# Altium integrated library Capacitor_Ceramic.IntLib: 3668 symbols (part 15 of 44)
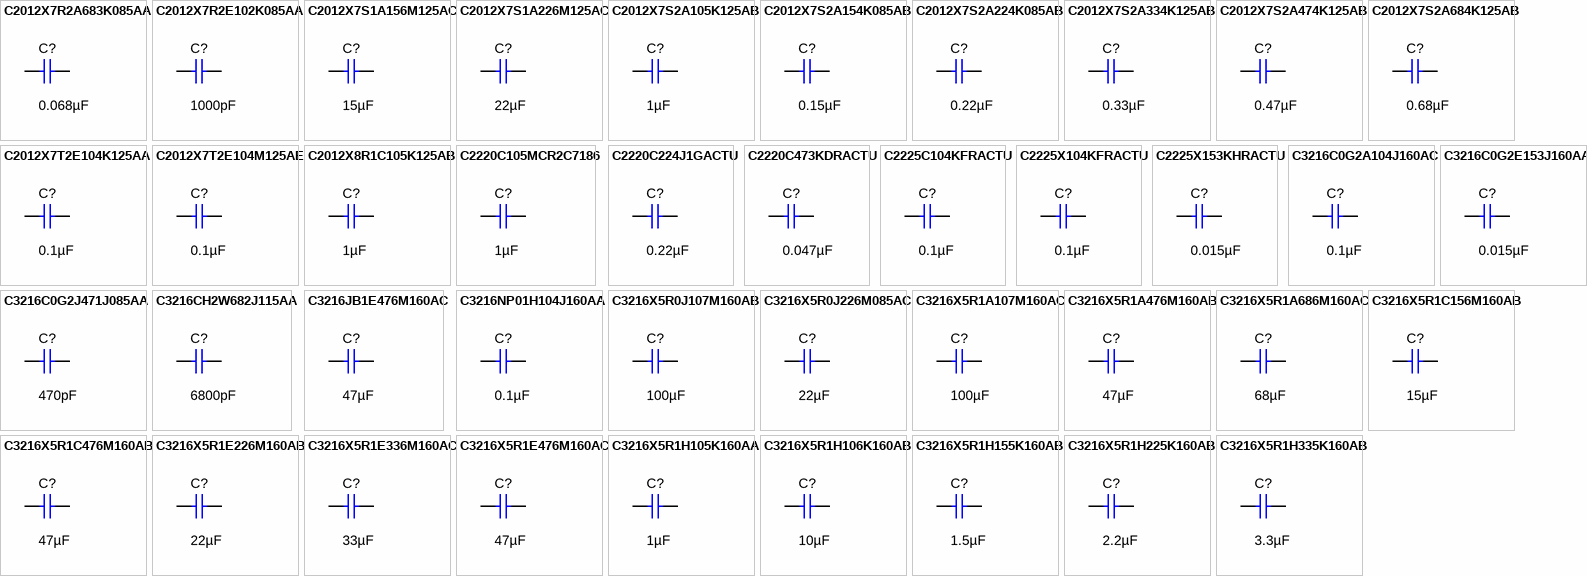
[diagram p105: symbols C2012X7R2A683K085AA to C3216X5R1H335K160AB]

## C2012X7R2A683K085AA
designator C?  ValueDisplayed: 0.068µF  (hidden comment: C2012X7R2A683K085AA)
CAP, CERM, 0.068 µF, 100 V,+/- 10%, X7R, 0805; Manufacturer: TDK; Polarized: N; CompType: Capacitor; Value: 0.068uF; U/M: EA; Cap_F: 0.000000068; Tolerance_%: 10; ESR_ohm: 0.027836; Value1: 0.027836 ohm; VDC_V: 100; Value2: 100V; IRMS_A: 1.26527; TaMin_C: -55; TaMax_C: 125; Cap_Case: 0805; SizeArea_mm2: 2.5; SizeAreaWB_mm2: 6.75; SizeX_mm: 2; SizeY_mm: 1.25; SizeZ_mm: 1.45; AEC Category: Q200
signal-integrity model Cap
simulation model Cap
footprint 0805_HV
footprint 0805_HV1
footprint 0805
footprint 0805M
footprint 0805L
pins: 1, 2

## C2012X7R2E102K085AA
designator C?  ValueDisplayed: 1000pF  (hidden comment: C2012X7R2E102K085AA)
CAP, CERM, 1000 pF, 250 V,+/- 10%, X7R, 0805; Manufacturer: TDK; Polarized: N; CompType: Capacitor; Value: 1000pF; U/M: EA; Cap_F: 0.000000001; Tolerance_%: 10; VDC_V: 250; Value2: 250V; TaMin_C: -55; TaMax_C: 125; Cap_Case: 0805; SizeArea_mm2: 2.5; SizeAreaWB_mm2: 6.75; SizeX_mm: 2; SizeY_mm: 1.25; SizeZ_mm: 1.45; AEC Category: Q200
signal-integrity model Cap
simulation model Cap
footprint 0805_HV
footprint 0805_HV1
footprint 0805
footprint 0805M
footprint 0805L
pins: 1, 2

## C2012X7S1A156M125AC
designator C?  ValueDisplayed: 15µF  (hidden comment: C2012X7S1A156M125AC)
CAP, CERM, 15 µF, 10 V,+/- 20%, X7S, 0805; Manufacturer: TDK; Polarized: N; CompType: Capacitor; Value: 15uF; U/M: EA; Cap_F: 0.000015; Tolerance_%: 20; ESR_ohm: 0.001669; Value1: 0.001669 ohm; VDC_V: 10; Value2: 10V; IRMS_A: 5.04984; TaMin_C: -55; TaMax_C: 125; Cap_Case: 0805; SizeArea_mm2: 2.5; SizeAreaWB_mm2: 6.75; SizeX_mm: 2; SizeY_mm: 1.25; SizeZ_mm: 1.45; AEC Category: Q200
signal-integrity model Cap
simulation model Cap
footprint 0805_HV
footprint 0805_HV1
footprint 0805
footprint 0805M
footprint 0805L
pins: 1, 2

## C2012X7S1A226M125AC
designator C?  ValueDisplayed: 22µF  (hidden comment: C2012X7S1A226M125AC)
CAP, CERM, 22 µF, 10 V,+/- 20%, X7S, 0805; Manufacturer: TDK; Polarized: N; CompType: Capacitor; Value: 22uF; U/M: EA; Cap_F: 0.000022; Tolerance_%: 20; ESR_ohm: 0.00205; Value1: 0.00205 ohm; VDC_V: 10; Value2: 10V; IRMS_A: 4.55587; TaMin_C: -55; TaMax_C: 125; Cap_Case: 0805; SizeArea_mm2: 2.5; SizeAreaWB_mm2: 6.75; SizeX_mm: 2; SizeY_mm: 1.25; SizeZ_mm: 1.45; AEC Category: Q200; Green_Lifecycle: Active; Green_REACh: Passed
signal-integrity model Cap
simulation model Cap
footprint 0805_HV
footprint 0805_HV1
footprint 0805
footprint 0805M
footprint 0805L
pins: 1, 2

## C2012X7S2A105K125AB
designator C?  ValueDisplayed: 1µF  (hidden comment: C2012X7S2A105K125AB)
CAP, CERM, 1 µF, 100 V,+/- 10%, X7S, 0805; Manufacturer: TDK; Polarized: N; CompType: Capacitor; Value: 1uF; U/M: EA; Cap_F: 0.000001; Tolerance_%: 10; ESR_ohm: 0.008255; Value1: 0.008255 ohm; VDC_V: 100; Value2: 100V; IRMS_A: 2.27442; TaMin_C: -55; TaMax_C: 125; Cap_Case: 0805; SizeArea_mm2: 2.5; SizeAreaWB_mm2: 6.75; SizeX_mm: 2; SizeY_mm: 1.25; SizeZ_mm: 1.45; AEC Category: Q200; Green_Lifecycle: Active; Green_REACh: Passed
signal-integrity model Cap
simulation model Cap
footprint 0805_HV
footprint 0805_HV1
footprint 0805
footprint 0805M
footprint 0805L
pins: 1, 2

## C2012X7S2A154K085AB
designator C?  ValueDisplayed: 0.15µF  (hidden comment: C2012X7S2A154K085AB)
CAP, CERM, 0.15 µF, 100 V,+/- 10%, X7S, 0805; Manufacturer: TDK; Polarized: N; CompType: Capacitor; Value: 0.15uF; U/M: EA; Cap_F: 0.00000015; Tolerance_%: 10; ESR_ohm: 0.043574; Value1: 0.043574 ohm; VDC_V: 100; Value2: 100V; IRMS_A: 0.999812; TaMin_C: -55; TaMax_C: 125; Cap_Case: 0805; SizeArea_mm2: 2.5; SizeAreaWB_mm2: 6.75; SizeX_mm: 2; SizeY_mm: 1.25; SizeZ_mm: 1.45; AEC Category: Q200
signal-integrity model Cap
simulation model Cap
footprint 0805_HV
footprint 0805_HV1
footprint 0805
footprint 0805M
footprint 0805L
pins: 1, 2

## C2012X7S2A224K085AB
designator C?  ValueDisplayed: 0.22µF  (hidden comment: C2012X7S2A224K085AB)
CAP, CERM, 0.22 µF, 100 V,+/- 10%, X7S, 0805; Manufacturer: TDK; Polarized: N; CompType: Capacitor; Value: 0.22uF; U/M: EA; Cap_F: 0.00000022; Tolerance_%: 10; ESR_ohm: 0.027015; Value1: 0.027015 ohm; VDC_V: 100; Value2: 100V; IRMS_A: 1.26497; TaMin_C: -55; TaMax_C: 125; Cap_Case: 0805; SizeArea_mm2: 2.5; SizeAreaWB_mm2: 6.75; SizeX_mm: 2; SizeY_mm: 1.25; SizeZ_mm: 1.45; AEC Category: Q200
signal-integrity model Cap
simulation model Cap
footprint 0805_HV
footprint 0805_HV1
footprint 0805
footprint 0805M
footprint 0805L
pins: 1, 2

## C2012X7S2A334K125AB
designator C?  ValueDisplayed: 0.33µF  (hidden comment: C2012X7S2A334K125AB)
CAP, CERM, 0.33 µF, 100 V,+/- 10%, X7S, 0805; Manufacturer: TDK; Polarized: N; CompType: Capacitor; Value: 0.33uF; U/M: EA; Cap_F: 0.00000033; Tolerance_%: 10; ESR_ohm: 0.019477; Value1: 0.019477 ohm; VDC_V: 100; Value2: 100V; IRMS_A: 1.48561; TaMin_C: -55; TaMax_C: 125; Cap_Case: 0805; SizeArea_mm2: 2.5; SizeAreaWB_mm2: 6.75; SizeX_mm: 2; SizeY_mm: 1.25; SizeZ_mm: 1.45; AEC Category: Q200
signal-integrity model Cap
simulation model Cap
footprint 0805_HV
footprint 0805_HV1
footprint 0805
footprint 0805M
footprint 0805L
pins: 1, 2

## C2012X7S2A474K125AB
designator C?  ValueDisplayed: 0.47µF  (hidden comment: C2012X7S2A474K125AB)
CAP, CERM, 0.47 µF, 100 V,+/- 10%, X7S, 0805; Manufacturer: TDK; Polarized: N; CompType: Capacitor; Value: 0.47uF; U/M: EA; Cap_F: 0.00000047; Tolerance_%: 10; ESR_ohm: 0.017152; Value1: 0.017152 ohm; VDC_V: 100; Value2: 100V; IRMS_A: 1.58068; TaMin_C: -55; TaMax_C: 125; Cap_Case: 0805; SizeArea_mm2: 2.5; SizeAreaWB_mm2: 6.75; SizeX_mm: 2; SizeY_mm: 1.25; SizeZ_mm: 1.45; AEC Category: Q200
signal-integrity model Cap
simulation model Cap
footprint 0805_HV
footprint 0805_HV1
footprint 0805
footprint 0805M
footprint 0805L
pins: 1, 2

## C2012X7S2A684K125AB
designator C?  ValueDisplayed: 0.68µF  (hidden comment: C2012X7S2A684K125AB)
CAP, CERM, 0.68 µF, 100 V,+/- 10%, X7S, 0805; Manufacturer: TDK; Polarized: N; CompType: Capacitor; Value: 0.68uF; U/M: EA; Cap_F: 0.00000068; Tolerance_%: 10; ESR_ohm: 0.009732; Value1: 0.009732 ohm; VDC_V: 100; Value2: 100V; IRMS_A: 2.09614; TaMin_C: -55; TaMax_C: 125; Cap_Case: 0805; SizeArea_mm2: 2.5; SizeAreaWB_mm2: 6.75; SizeX_mm: 2; SizeY_mm: 1.25; SizeZ_mm: 1.45; AEC Category: Q200
signal-integrity model Cap
simulation model Cap
footprint 0805_HV
footprint 0805_HV1
footprint 0805
footprint 0805M
footprint 0805L
pins: 1, 2

## C2012X7T2E104K125AA
designator C?  ValueDisplayed: 0.1µF  (hidden comment: C2012X7T2E104K125AA)
CAP, CERM, 0.1 µF, 250 V,+/- 10%, X7T, 0805; Manufacturer: TDK; Polarized: N; CompType: Capacitor; Value: 0.1uF; U/M: EA; Cap_F: 0.0000001; Tolerance_%: 10; VDC_V: 250; Value2: 250V; TaMin_C: -55; TaMax_C: 125; Cap_Case: 0805; SizeArea_mm2: 2.5; SizeAreaWB_mm2: 6.75; SizeX_mm: 2; SizeY_mm: 1.25; SizeZ_mm: 1.45; AEC Category: Q200
signal-integrity model Cap
simulation model Cap
footprint 0805_HV
footprint 0805_HV1
footprint 0805
footprint 0805M
footprint 0805L
pins: 1, 2

## C2012X7T2E104M125AE
designator C?  ValueDisplayed: 0.1µF  (hidden comment: C2012X7T2E104M125AE)
CAP, CERM, 0.1 µF, 250 V,+/- 20%, X7T, 0805; Manufacturer: TDK; Polarized: N; CompType: Capacitor; Value: 0.1uF; U/M: EA; Cap_F: 0.0000001; Tolerance_%: 20; VDC_V: 250; Value2: 250V; TaMin_C: -55; TaMax_C: 125; Cap_Case: 0805; SizeArea_mm2: 2.5; SizeAreaWB_mm2: 6.75; SizeX_mm: 2; SizeY_mm: 1.25; SizeZ_mm: 1.45; AEC Category: Q200
signal-integrity model Cap
simulation model Cap
footprint 0805_HV
footprint 0805_HV1
footprint 0805
footprint 0805M
footprint 0805L
pins: 1, 2

## C2012X8R1C105K125AB
designator C?  ValueDisplayed: 1µF  (hidden comment: C2012X8R1C105K125AB)
CAP, CERM, 1 µF, 16 V,+/- 10%, X8R, 0805; Manufacturer: TDK; Polarized: N; CompType: Capacitor; Value: 1uF; U/M: EA; Cap_F: 0.000001; Tolerance_%: 10; VDC_V: 16; Value2: 16V; TaMin_C: -55; TaMax_C: 150; Cap_Case: 0805; SizeArea_mm2: 2.5; SizeAreaWB_mm2: 6.75; SizeX_mm: 2; SizeY_mm: 1.25; SizeZ_mm: 1.45; AEC Category: Q200
signal-integrity model Cap
simulation model Cap
footprint 0805_HV
footprint 0805_HV1
footprint 0805
footprint 0805M
footprint 0805L
pins: 1, 2

## C2220C105MCR2C7186
designator C?  ValueDisplayed: 1µF  (hidden comment: C2220C105MCR2C7186)
CAP, CERM, 1 µF, 500 V,+/- 20%, X7R, AEC-Q200 Grade 1, 6x5mm; Manufacturer: Kemet; Polarized: N; CompType: Capacitor; Value: 1uF; U/M: EA; Cap_F: 0.000001; Tolerance_%: 20; VDC_V: 500; Value2: 500V; TaMin_C: -55; TaMax_C: 125; Cap_Case: 2220; SizeArea_mm2: 30; SizeAreaWB_mm2: 56; SizeX_mm: 6; SizeY_mm: 5; AEC Category: Q200; AEC Qualified: Y; AEC Grade: 1; Green_Lifecycle: Not Set; Green_REACh: Incomplete
signal-integrity model Cap
simulation model Cap
footprint KPS_600x500x500
pins: 1, 2

## C2220C224J1GACTU
designator C?  ValueDisplayed: 0.22µF  (hidden comment: C2220C224J1GACTU)
CAP, CERM, 0.22 µF, 100 V,+/- 5%, C0G/NP0, 2220; Manufacturer: Kemet; Polarized: N; CompType: Capacitor; Value: 0.22uF; U/M: EA; Cap_F: 0.00000022; Tolerance_%: 5; VDC_V: 100; Value2: 100V; TaMin_C: -55; TaMax_C: 125; Cap_Case: 2220; SizeArea_mm2: 28.5; SizeAreaWB_mm2: 53.9; SizeX_mm: 5.7; SizeZ_mm: 1.5; AEC Category: Q200; Green_Lifecycle: Active; Green_REACh: Passed
signal-integrity model Cap
simulation model Cap
footprint 2220_150
footprint 2220_150M
footprint 2220_150L
pins: 1, 2

## C2220C473KDRACTU
designator C?  ValueDisplayed: 0.047µF  (hidden comment: C2220C473KDRACTU)
CAP, CERM, 0.047 µF, 1000 V,+/- 10%, X7R, 2220; Manufacturer: Kemet; Polarized: N; CompType: Capacitor; Value: 0.047uF; U/M: EA; Cap_F: 0.000000047; Tolerance_%: 10; VDC_V: 1000; Value2: 1000V; TaMin_C: -55; TaMax_C: 125; Cap_Case: 2220; SizeArea_mm2: 28.5; SizeAreaWB_mm2: 53.9; SizeX_mm: 5.7; SizeY_mm: 5; SizeZ_mm: 1.8; AEC Category: Q200; Green_Lifecycle: Not Set; Green_REACh: Incomplete
signal-integrity model Cap
simulation model Cap
footprint 2220_180
footprint 2220_180M
footprint 2220_180L
pins: 1, 2

## C2225C104KFRACTU
designator C?  ValueDisplayed: 0.1µF  (hidden comment: C2225C104KFRACTU)
CAP, CERM, 0.1 µF, 1500 V,+/- 10%, X7R, 2225; Manufacturer: Kemet; Polarized: N; CompType: Capacitor; Value: 0.1uF; U/M: EA; Cap_F: 0.0000001; Tolerance_%: 10; VDC_V: 1500; Value2: 1500V; TaMin_C: -55; TaMax_C: 125; Cap_Case: 2225; SizeArea_mm2: 35.91; SizeAreaWB_mm2: 63.91; SizeX_mm: 5.7; SizeY_mm: 6.3; SizeZ_mm: 2; AEC Category: Q200; Green_Lifecycle: Not Set; Green_REACh: Incomplete
signal-integrity model Cap
simulation model Cap
footprint 2225
footprint 2225_M
footprint 2225_L
pins: 1, 2

## C2225X104KFRACTU
designator C?  ValueDisplayed: 0.1µF  (hidden comment: C2225X104KFRACTU)
CAP, CERM, 0.1 µF, 1500 V,+/- 10%, X7R, 2225; Manufacturer: Kemet; Polarized: N; CompType: Capacitor; Value: 0.1uF; U/M: EA; Cap_F: 0.0000001; Tolerance_%: 10; VDC_V: 1500; Value2: 1500V; TaMin_C: -55; TaMax_C: 125; Cap_Case: 2225; SizeArea_mm2: 35.91; SizeAreaWB_mm2: 63.91; SizeX_mm: 5.7; SizeY_mm: 6.3; SizeZ_mm: 2.7; AEC Category: Q200; Green_Lifecycle: Not Set; Green_REACh: Incomplete
signal-integrity model Cap
simulation model Cap
footprint 2225_270
footprint 2225_270_M
footprint 2225_270_L
pins: 1, 2

## C2225X153KHRACTU
designator C?  ValueDisplayed: 0.015µF  (hidden comment: C2225X153KHRACTU)
CAP, CERM, 0.015 µF, 3000 V,+/- 10%, X7R, 2225; Manufacturer: Kemet; Polarized: N; CompType: Capacitor; Value: 0.015uF; U/M: EA; Cap_F: 0.000000015; Tolerance_%: 10; VDC_V: 3000; Value2: 3000V; TaMin_C: -55; TaMax_C: 125; Cap_Case: 2225; SizeArea_mm2: 35.91; SizeAreaWB_mm2: 63.91; SizeX_mm: 5.7; SizeY_mm: 6.3; SizeZ_mm: 2.7; AEC Category: Q200; Green_Lifecycle: Not Set; Green_REACh: Incomplete
signal-integrity model Cap
simulation model Cap
footprint 2225_270
footprint 2225_270_M
footprint 2225_270_L
pins: 1, 2

## C3216C0G2A104J160AC
designator C?  ValueDisplayed: 0.1µF  (hidden comment: C3216C0G2A104J160AC)
CAP, CERM, 0.1 µF, 100 V,+/- 5%, C0G/NP0, 1206; Manufacturer: TDK; Polarized: N; CompType: Capacitor; Value: 0.1uF; U/M: EA; Cap_F: 0.0000001; Tolerance_%: 5; VDC_V: 100; Value2: 100V; TaMin_C: -55; TaMax_C: 125; Cap_Case: 1206; SizeArea_mm2: 5.12; SizeAreaWB_mm2: 10.92; SizeX_mm: 3.2; SizeY_mm: 1.6; SizeZ_mm: 1.9; AEC Category: Q200
signal-integrity model Cap
simulation model Cap
footprint 1206_190
footprint 1206_190M
footprint 1206_190L
pins: 1, 2

## C3216C0G2E153J160AA
designator C?  ValueDisplayed: 0.015µF  (hidden comment: C3216C0G2E153J160AA)
CAP, CERM, 0.015 µF, 250 V,+/- 5%, C0G/NP0, 1206; Manufacturer: TDK; Polarized: N; CompType: Capacitor; Value: 0.015uF; U/M: EA; Cap_F: 0.000000015; Tolerance_%: 5; VDC_V: 250; Value2: 250V; TaMin_C: -55; TaMax_C: 125; Cap_Case: 1206; SizeArea_mm2: 5.12; SizeAreaWB_mm2: 10.92; SizeX_mm: 3.2; SizeY_mm: 1.6; SizeZ_mm: 1.9; AEC Category: Q200
signal-integrity model Cap
simulation model Cap
footprint 1206_190
footprint 1206_190M
footprint 1206_190L
pins: 1, 2

## C3216C0G2J471J085AA
designator C?  ValueDisplayed: 470pF  (hidden comment: C3216C0G2J471J085AA)
CAP, CERM, 470 pF, 630 V,+/- 5%, C0G/NP0, 1206; Manufacturer: TDK; Polarized: N; CompType: Capacitor; Value: 470pF; U/M: EA; Cap_F: 0.00000000047; Tolerance_%: 5; VDC_V: 630; Value2: 630V; TaMin_C: -55; TaMax_C: 125; Cap_Case: 1206; SizeArea_mm2: 5.12; SizeAreaWB_mm2: 10.92; SizeX_mm: 3.2; SizeY_mm: 1.6; SizeZ_mm: 1.35; AEC Category: Q200; Green_Lifecycle: Active; Green_REACh: Passed
signal-integrity model Cap
simulation model Cap
footprint 1206
footprint 1206M
footprint 1206L
pins: 1, 2

## C3216CH2W682J115AA
designator C?  ValueDisplayed: 6800pF  (hidden comment: C3216CH2W682J115AA)
CAP, CERM, 6800 pF, 450 V,+/- 5%, CH, 1206; Manufacturer: TDK; Polarized: N; CompType: Capacitor; Value: 6800pF; U/M: EA; Cap_F: 0.0000000068; Tolerance_%: 5; VDC_V: 450; Value2: 450V; TaMin_C: -25; TaMax_C: 85; Cap_Case: 1206; SizeArea_mm2: 5.12; SizeAreaWB_mm2: 10.92; SizeX_mm: 3.2; SizeY_mm: 1.6; SizeZ_mm: 1.4; AEC Category: Q200
signal-integrity model Cap
simulation model Cap
footprint 1206_140
footprint 1206_140M
footprint 1206_140L
pins: 1, 2

## C3216JB1E476M160AC
designator C?  ValueDisplayed: 47µF  (hidden comment: C3216JB1E476M160AC)
CAP, CERM, 47 µF, 25 V,+/- 20%, JB, 1206; Manufacturer: TDK; Polarized: N; CompType: Capacitor; Value: 47uF; U/M: EA; Cap_F: 0.000047; Tolerance_%: 20; VDC_V: 25; Value2: 25V; TaMin_C: -55; TaMax_C: 85; Cap_Case: 1206; SizeArea_mm2: 5.12; SizeAreaWB_mm2: 10.92; SizeX_mm: 3.2; SizeY_mm: 1.6; SizeZ_mm: 1.35; AEC Category: Q200
signal-integrity model Cap
simulation model Cap
footprint 1206
footprint 1206M
footprint 1206L
pins: 1, 2

## C3216NP01H104J160AA
designator C?  ValueDisplayed: 0.1µF  (hidden comment: C3216NP01H104J160AA)
CAP, CERM, 0.1 µF, 50 V,+/- 5%, C0G/NP0, 1206; Manufacturer: TDK; Polarized: N; CompType: Capacitor; Value: 0.1uF; U/M: EA; Cap_F: 0.0000001; Tolerance_%: 5; VDC_V: 50; Value2: 50V; TaMin_C: -55; TaMax_C: 150; Cap_Case: 1206; SizeArea_mm2: 5.12; SizeAreaWB_mm2: 10.92; SizeX_mm: 3.2; SizeY_mm: 1.6; SizeZ_mm: 1.9; AEC Category: Q200
signal-integrity model Cap
simulation model Cap
footprint 1206_190
footprint 1206_190M
footprint 1206_190L
pins: 1, 2

## C3216X5R0J107M160AB
designator C?  ValueDisplayed: 100µF  (hidden comment: C3216X5R0J107M160AB)
CAP, CERM, 100 µF, 6.3 V,+/- 20%, X5R, 1206; Manufacturer: TDK; Polarized: N; CompType: Capacitor; Value: 100uF; U/M: EA; Cap_F: 0.0001; Tolerance_%: 20; VDC_V: 6.3; Value2: 6.3V; TaMin_C: -55; TaMax_C: 85; Cap_Case: 1206; SizeArea_mm2: 5.12; SizeAreaWB_mm2: 10.92; SizeX_mm: 3.2; SizeY_mm: 1.6; SizeZ_mm: 1.9; AEC Category: Q200; Green_Lifecycle: Active; Green_REACh: Passed
signal-integrity model Cap
simulation model Cap
footprint 1206_190
footprint 1206_190M
footprint 1206_190L
pins: 1, 2

## C3216X5R0J226M085AC
designator C?  ValueDisplayed: 22µF  (hidden comment: C3216X5R0J226M085AC)
CAP, CERM, 22 µF, 6.3 V,+/- 20%, X5R, 1206; Manufacturer: TDK; Polarized: N; CompType: Capacitor; Value: 22uF; U/M: EA; Cap_F: 0.000022; Tolerance_%: 20; ESR_ohm: 0.002; Value1: 0.002 ohm; VDC_V: 6.3; Value2: 6.3V; IRMS_A: 3.62; TaMin_C: -55; TaMax_C: 85; Cap_Case: 1206; SizeArea_mm2: 5.12; SizeAreaWB_mm2: 10.92; SizeX_mm: 3.2; SizeY_mm: 1.6; SizeZ_mm: 1.35; AEC Category: Q200; Green_Lifecycle: NRND; Green_REACh: Passed
signal-integrity model Cap
simulation model Cap
footprint 1206
footprint 1206M
footprint 1206L
pins: 1, 2

## C3216X5R1A107M160AC
designator C?  ValueDisplayed: 100µF  (hidden comment: C3216X5R1A107M160AC)
CAP, CERM, 100 µF, 10 V,+/- 20%, X5R, 1206; Manufacturer: TDK; Polarized: N; CompType: Capacitor; Value: 100uF; U/M: EA; Cap_F: 0.0001; Tolerance_%: 20; ESR_ohm: 0.002838; Value1: 0.002838 ohm; VDC_V: 10; Value2: 10V; IRMS_A: 4.30694; TaMin_C: -55; TaMax_C: 85; Cap_Case: 1206; SizeArea_mm2: 5.12; SizeAreaWB_mm2: 10.92; SizeX_mm: 3.2; SizeY_mm: 1.6; SizeZ_mm: 1.9; AEC Category: Q200; Green_Lifecycle: Active; Green_REACh: Passed
signal-integrity model Cap
simulation model Cap
footprint 1206_190
footprint 1206_190M
footprint 1206_190L
pins: 1, 2

## C3216X5R1A476M160AB
designator C?  ValueDisplayed: 47µF  (hidden comment: C3216X5R1A476M160AB)
CAP, CERM, 47 µF, 10 V,+/- 20%, X5R, 1206; Manufacturer: TDK; Polarized: N; CompType: Capacitor; Value: 47uF; U/M: EA; Cap_F: 0.000047; Tolerance_%: 20; VDC_V: 10; Value2: 10V; TaMin_C: -55; TaMax_C: 85; Cap_Case: 1206; SizeArea_mm2: 5.12; SizeAreaWB_mm2: 10.92; SizeX_mm: 3.2; SizeY_mm: 1.6; SizeZ_mm: 1.8; AEC Category: Q200
signal-integrity model Cap
simulation model Cap
footprint 1206_180
footprint 1206_180M
footprint 1206_180L
pins: 1, 2

## C3216X5R1A686M160AC
designator C?  ValueDisplayed: 68µF  (hidden comment: C3216X5R1A686M160AC)
CAP, CERM, 68 µF, 10 V,+/- 20%, X5R, 1206; Manufacturer: TDK; Polarized: N; CompType: Capacitor; Value: 68uF; U/M: EA; Cap_F: 0.000068; Tolerance_%: 20; ESR_ohm: 0.003494; Value1: 0.003494 ohm; VDC_V: 10; Value2: 10V; IRMS_A: 3.8813; TaMin_C: -55; TaMax_C: 85; Cap_Case: 1206; SizeArea_mm2: 5.12; SizeAreaWB_mm2: 10.92; SizeX_mm: 3.2; SizeY_mm: 1.6; SizeZ_mm: 1.9; AEC Category: Q200
signal-integrity model Cap
simulation model Cap
footprint 1206_190
footprint 1206_190M
footprint 1206_190L
pins: 1, 2

## C3216X5R1C156M160AB
designator C?  ValueDisplayed: 15µF  (hidden comment: C3216X5R1C156M160AB)
CAP, CERM, 15 µF, 16 V,+/- 20%, X5R, 1206; Manufacturer: TDK; Polarized: N; CompType: Capacitor; Value: 15uF; U/M: EA; Cap_F: 0.000015; Tolerance_%: 20; VDC_V: 16; Value2: 16V; TaMin_C: -55; TaMax_C: 85; Cap_Case: 1206; SizeArea_mm2: 5.12; SizeAreaWB_mm2: 10.92; SizeX_mm: 3.2; SizeY_mm: 1.6; SizeZ_mm: 1.8; AEC Category: Q200; Green_Lifecycle: Not Set; Green_REACh: Incomplete
signal-integrity model Cap
simulation model Cap
footprint 1206_180
footprint 1206_180M
footprint 1206_180L
pins: 1, 2

## C3216X5R1C476M160AB
designator C?  ValueDisplayed: 47µF  (hidden comment: C3216X5R1C476M160AB)
CAP, CERM, 47 µF, 16 V,+/- 15%, X5R, 1206; Manufacturer: TDK; Polarized: N; CompType: Capacitor; Value: 47uF; U/M: EA; Cap_F: 0.000047; Tolerance_%: 15; VDC_V: 16; Value2: 16V; TaMin_C: -55; TaMax_C: 85; Cap_Case: 1206; SizeArea_mm2: 5.12; SizeAreaWB_mm2: 10.92; SizeX_mm: 3.2; SizeY_mm: 1.6; SizeZ_mm: 1.35; AEC Category: Q200; Green_Lifecycle: Active; Green_REACh: Passed
signal-integrity model Cap
simulation model Cap
footprint 1206
footprint 1206M
footprint 1206L
pins: 1, 2

## C3216X5R1E226M160AB
designator C?  ValueDisplayed: 22µF  (hidden comment: C3216X5R1E226M160AB)
CAP, CERM, 22 µF, 25 V,+/- 20%, X5R, 1206; Manufacturer: TDK; Polarized: N; CompType: Capacitor; Value: 22uF; U/M: EA; Cap_F: 0.000022; Tolerance_%: 20; VDC_V: 25; Value2: 25V; TaMin_C: -55; TaMax_C: 85; Cap_Case: 1206; SizeArea_mm2: 5.12; SizeAreaWB_mm2: 10.92; SizeX_mm: 3.2; SizeY_mm: 1.6; SizeZ_mm: 1.9; AEC Category: Q200; Green_Lifecycle: Active; Green_REACh: Passed
signal-integrity model Cap
simulation model Cap
footprint 1206_190
footprint 1206_190M
footprint 1206_190L
pins: 1, 2

## C3216X5R1E336M160AC
designator C?  ValueDisplayed: 33µF  (hidden comment: C3216X5R1E336M160AC)
CAP, CERM, 33 µF, 25 V,+/- 20%, X5R, 1206; Manufacturer: TDK; Polarized: N; CompType: Capacitor; Value: 33uF; U/M: EA; Cap_F: 0.000033; Tolerance_%: 20; ESR_ohm: 0.002648; Value1: 0.002648 ohm; VDC_V: 25; Value2: 25V; IRMS_A: 4.45864; TaMin_C: -55; TaMax_C: 85; Cap_Case: 1206; SizeArea_mm2: 5.12; SizeAreaWB_mm2: 10.92; SizeX_mm: 3.2; SizeY_mm: 1.6; SizeZ_mm: 1.8; AEC Category: Q200; Green_Lifecycle: Active; Green_REACh: Passed
signal-integrity model Cap
simulation model Cap
footprint 1206_180
footprint 1206_180M
footprint 1206_180L
pins: 1, 2

## C3216X5R1E476M160AC
designator C?  ValueDisplayed: 47µF  (hidden comment: C3216X5R1E476M160AC)
CAP, CERM, 47 µF, 25 V,+/- 20%, X5R, 1206; Manufacturer: TDK; Polarized: N; CompType: Capacitor; Value: 47uF; U/M: EA; Cap_F: 0.000047; Tolerance_%: 20; VDC_V: 25; Value2: 25V; TaMin_C: -55; TaMax_C: 85; Cap_Case: 1206; SizeArea_mm2: 5.12; SizeAreaWB_mm2: 10.92; SizeX_mm: 3.2; SizeY_mm: 1.6; SizeZ_mm: 1.9; AEC Category: Q200; Green_Lifecycle: Active; Green_REACh: Passed
signal-integrity model Cap
simulation model Cap
footprint 1206_190
footprint 1206_190M
footprint 1206_190L
pins: 1, 2

## C3216X5R1H105K160AA
designator C?  ValueDisplayed: 1µF  (hidden comment: C3216X5R1H105K160AA)
CAP, CERM, 1 µF, 50 V,+/- 10%, X5R, 1206; Manufacturer: TDK; Polarized: N; CompType: Capacitor; Value: 1uF; U/M: EA; Cap_F: 0.000001; Tolerance_%: 10; ESR_ohm: 0.009289; Value1: 0.009289 ohm; VDC_V: 50; Value2: 50V; IRMS_A: 2.38446; TaMin_C: -55; TaMax_C: 85; Cap_Case: 1206; SizeArea_mm2: 5.12; SizeAreaWB_mm2: 10.92; SizeX_mm: 3.2; SizeY_mm: 1.6; SizeZ_mm: 1.8; AEC Category: Q200
signal-integrity model Cap
simulation model Cap
footprint 1206_180
footprint 1206_180M
footprint 1206_180L
pins: 1, 2

## C3216X5R1H106K160AB
designator C?  ValueDisplayed: 10µF  (hidden comment: C3216X5R1H106K160AB)
CAP, CERM, 10 µF, 50 V,+/- 10%, X5R, 1206; Manufacturer: TDK; Polarized: N; CompType: Capacitor; Value: 10uF; U/M: EA; Cap_F: 0.00001; Tolerance_%: 10; ESR_ohm: 0.002229; Value1: 0.002229 ohm; VDC_V: 50; Value2: 50V; IRMS_A: 4.85932; TaMin_C: -55; TaMax_C: 85; Cap_Case: 1206; SizeArea_mm2: 5.12; SizeAreaWB_mm2: 10.92; SizeX_mm: 3.2; SizeY_mm: 1.6; SizeZ_mm: 1.8; AEC Category: Q200; Green_Lifecycle: Active; Green_REACh: Passed
signal-integrity model Cap
simulation model Cap
footprint 1206_180
footprint 1206_180M
footprint 1206_180L
pins: 1, 2

## C3216X5R1H155K160AB
designator C?  ValueDisplayed: 1.5µF  (hidden comment: C3216X5R1H155K160AB)
CAP, CERM, 1.5 µF, 50 V,+/- 10%, X5R, 1206; Manufacturer: TDK; Polarized: N; CompType: Capacitor; Value: 1.5uF; U/M: EA; Cap_F: 0.0000015; Tolerance_%: 10; ESR_ohm: 0.007741; Value1: 0.007741 ohm; VDC_V: 50; Value2: 50V; IRMS_A: 2.61033; TaMin_C: -55; TaMax_C: 85; Cap_Case: 1206; SizeArea_mm2: 5.12; SizeAreaWB_mm2: 10.92; SizeX_mm: 3.2; SizeY_mm: 1.6; SizeZ_mm: 1.8; AEC Category: Q200
signal-integrity model Cap
simulation model Cap
footprint 1206_180
footprint 1206_180M
footprint 1206_180L
pins: 1, 2

## C3216X5R1H225K160AB
designator C?  ValueDisplayed: 2.2µF  (hidden comment: C3216X5R1H225K160AB)
CAP, CERM, 2.2 µF, 50 V,+/- 10%, X5R, 1206; Manufacturer: TDK; Polarized: N; CompType: Capacitor; Value: 2.2uF; U/M: EA; Cap_F: 0.0000022; Tolerance_%: 10; ESR_ohm: 0.005887; Value1: 0.005887 ohm; VDC_V: 50; Value2: 50V; IRMS_A: 2.99226; TaMin_C: -55; TaMax_C: 85; Cap_Case: 1206; SizeArea_mm2: 5.12; SizeAreaWB_mm2: 10.92; SizeX_mm: 3.2; SizeY_mm: 1.6; SizeZ_mm: 1.8; AEC Category: Q200
signal-integrity model Cap
simulation model Cap
footprint 1206_180
footprint 1206_180M
footprint 1206_180L
pins: 1, 2

## C3216X5R1H335K160AB
designator C?  ValueDisplayed: 3.3µF  (hidden comment: C3216X5R1H335K160AB)
CAP, CERM, 3.3 µF, 50 V,+/- 10%, X5R, 1206; Manufacturer: TDK; Polarized: N; CompType: Capacitor; Value: 3.3uF; U/M: EA; Cap_F: 0.0000033; Tolerance_%: 10; ESR_ohm: 0.004773; Value1: 0.004773 ohm; VDC_V: 50; Value2: 50V; IRMS_A: 3.3221; TaMin_C: -55; TaMax_C: 85; Cap_Case: 1206; SizeArea_mm2: 5.12; SizeAreaWB_mm2: 10.92; SizeX_mm: 3.2; SizeY_mm: 1.6; SizeZ_mm: 1.8; AEC Category: Q200
signal-integrity model Cap
simulation model Cap
footprint 1206_180
footprint 1206_180M
footprint 1206_180L
pins: 1, 2

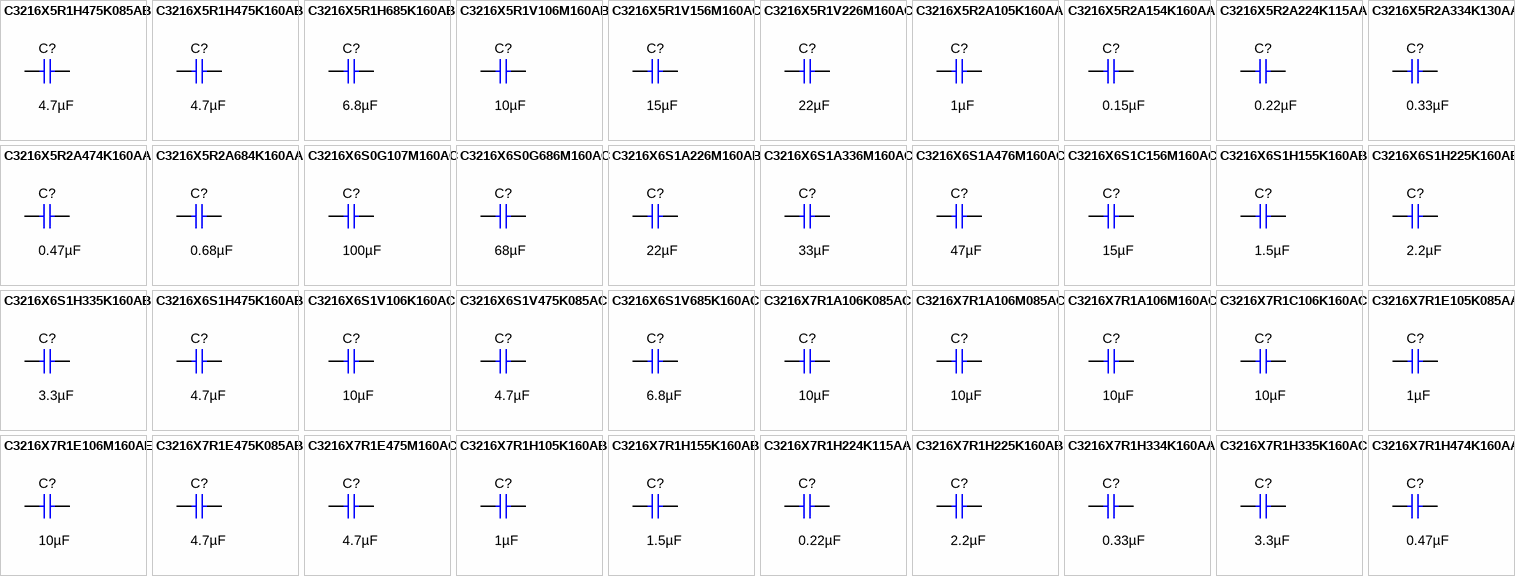
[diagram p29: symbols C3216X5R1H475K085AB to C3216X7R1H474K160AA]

## C3216X5R1H475K085AB
designator C?  ValueDisplayed: 4.7µF  (hidden comment: C3216X5R1H475K085AB)
CAP, CERM, 4.7 µF, 50 V,+/- 10%, X5R, 1206; Manufacturer: TDK; Polarized: N; CompType: Capacitor; Value: 4.7uF; U/M: EA; Cap_F: 0.0000047; Tolerance_%: 10; ESR_ohm: 0.003785; Value1: 0.003785 ohm; VDC_V: 50; Value2: 50V; IRMS_A: 3.73011; TaMin_C: -55; TaMax_C: 85; Cap_Case: 1206; SizeArea_mm2: 5.12; SizeAreaWB_mm2: 10.92; SizeX_mm: 3.2; SizeY_mm: 1.6; SizeZ_mm: 1.35; AEC Category: Q200
signal-integrity model Cap
simulation model Cap
footprint 1206
footprint 1206M
footprint 1206L
pins: 1, 2

## C3216X5R1H475K160AB
designator C?  ValueDisplayed: 4.7µF  (hidden comment: C3216X5R1H475K160AB)
CAP, CERM, 4.7 µF, 50 V,+/- 10%, X5R, 1206; Manufacturer: TDK; Polarized: N; CompType: Capacitor; Value: 4.7uF; U/M: EA; Cap_F: 0.0000047; Tolerance_%: 10; ESR_ohm: 0.003158; Value1: 0.003158 ohm; VDC_V: 50; Value2: 50V; IRMS_A: 4.08379; TaMin_C: -55; TaMax_C: 85; Cap_Case: 1206; SizeArea_mm2: 5.12; SizeAreaWB_mm2: 10.92; SizeX_mm: 3.2; SizeY_mm: 1.6; SizeZ_mm: 1.8; AEC Category: Q200
signal-integrity model Cap
simulation model Cap
footprint 1206_180
footprint 1206_180M
footprint 1206_180L
pins: 1, 2

## C3216X5R1H685K160AB
designator C?  ValueDisplayed: 6.8µF  (hidden comment: C3216X5R1H685K160AB)
CAP, CERM, 6.8 µF, 50 V,+/- 10%, X5R, 1206; Manufacturer: TDK; Polarized: N; CompType: Capacitor; Value: 6.8uF; U/M: EA; Cap_F: 0.0000068; Tolerance_%: 10; ESR_ohm: 0.003202; Value1: 0.003202 ohm; VDC_V: 50; Value2: 50V; IRMS_A: 4.05527; TaMin_C: -55; TaMax_C: 85; Cap_Case: 1206; SizeArea_mm2: 5.12; SizeAreaWB_mm2: 10.92; SizeX_mm: 3.2; SizeY_mm: 1.6; SizeZ_mm: 1.8; AEC Category: Q200
signal-integrity model Cap
simulation model Cap
footprint 1206_180
footprint 1206_180M
footprint 1206_180L
pins: 1, 2

## C3216X5R1V106M160AB
designator C?  ValueDisplayed: 10µF  (hidden comment: C3216X5R1V106M160AB)
CAP, CERM, 10 µF, 35 V,+/- 20%, X5R, 1206; Manufacturer: TDK; Polarized: N; CompType: Capacitor; Value: 10uF; U/M: EA; Cap_F: 0.00001; Tolerance_%: 20; VDC_V: 35; Value2: 35V; TaMin_C: -55; TaMax_C: 85; Cap_Case: 1206; SizeArea_mm2: 5.12; SizeAreaWB_mm2: 10.92; SizeX_mm: 3.2; SizeY_mm: 1.6; SizeZ_mm: 1.8; AEC Category: Q200; Green_Lifecycle: Not Set; Green_REACh: Incomplete
signal-integrity model Cap
simulation model Cap
footprint 1206_180
footprint 1206_180M
footprint 1206_180L
pins: 1, 2

## C3216X5R1V156M160AC
designator C?  ValueDisplayed: 15µF  (hidden comment: C3216X5R1V156M160AC)
CAP, CERM, 15 µF, 35 V,+/- 20%, X5R, 1206; Manufacturer: TDK; Polarized: N; CompType: Capacitor; Value: 15uF; U/M: EA; Cap_F: 0.000015; Tolerance_%: 20; ESR_ohm: 0.002667; Value1: 0.002667 ohm; VDC_V: 35; Value2: 35V; IRMS_A: 4.44289; TaMin_C: -55; TaMax_C: 85; Cap_Case: 1206; SizeArea_mm2: 5.12; SizeAreaWB_mm2: 10.92; SizeX_mm: 3.2; SizeY_mm: 1.6; SizeZ_mm: 1.8; AEC Category: Q200
signal-integrity model Cap
simulation model Cap
footprint 1206_180
footprint 1206_180M
footprint 1206_180L
pins: 1, 2

## C3216X5R1V226M160AC
designator C?  ValueDisplayed: 22µF  (hidden comment: C3216X5R1V226M160AC)
CAP, CERM, 22 µF, 35 V,+/- 20%, X5R, 1206; Manufacturer: TDK; Polarized: N; CompType: Capacitor; Value: 22uF; U/M: EA; Cap_F: 0.000022; Tolerance_%: 20; ESR_ohm: 0.002398; Value1: 0.002398 ohm; VDC_V: 35; Value2: 35V; IRMS_A: 4.68507; TaMin_C: -55; TaMax_C: 85; Cap_Case: 1206; SizeArea_mm2: 5.12; SizeAreaWB_mm2: 10.92; SizeX_mm: 3.2; SizeY_mm: 1.6; SizeZ_mm: 1.8; AEC Category: Q200; Green_Lifecycle: Active; Green_REACh: Passed
signal-integrity model Cap
simulation model Cap
footprint 1206_180
footprint 1206_180M
footprint 1206_180L
pins: 1, 2

## C3216X5R2A105K160AA
designator C?  ValueDisplayed: 1µF  (hidden comment: C3216X5R2A105K160AA)
CAP, CERM, 1 µF, 100 V,+/- 10%, X5R, 1206; Manufacturer: TDK; Polarized: N; CompType: Capacitor; Value: 1uF; U/M: EA; Cap_F: 0.000001; Tolerance_%: 10; ESR_ohm: 0.004575; Value1: 0.004575 ohm; VDC_V: 100; Value2: 100V; IRMS_A: 3.39639; TaMin_C: -55; TaMax_C: 85; Cap_Case: 1206; SizeArea_mm2: 5.12; SizeAreaWB_mm2: 10.92; SizeX_mm: 3.2; SizeY_mm: 1.6; SizeZ_mm: 1.8; AEC Category: Q200
signal-integrity model Cap
simulation model Cap
footprint 1206_180
footprint 1206_180M
footprint 1206_180L
pins: 1, 2

## C3216X5R2A154K160AA
designator C?  ValueDisplayed: 0.15µF  (hidden comment: C3216X5R2A154K160AA)
CAP, CERM, 0.15 µF, 100 V,+/- 10%, X5R, 1206; Manufacturer: TDK; Polarized: N; CompType: Capacitor; Value: 0.15uF; U/M: EA; Cap_F: 0.00000015; Tolerance_%: 10; ESR_ohm: 0.021684; Value1: 0.021684 ohm; VDC_V: 100; Value2: 100V; IRMS_A: 1.57495; TaMin_C: -55; TaMax_C: 85; Cap_Case: 1206; SizeArea_mm2: 5.12; SizeAreaWB_mm2: 10.92; SizeX_mm: 3.2; SizeY_mm: 1.6; SizeZ_mm: 1.8; AEC Category: Q200
signal-integrity model Cap
simulation model Cap
footprint 1206_180
footprint 1206_180M
footprint 1206_180L
pins: 1, 2

## C3216X5R2A224K115AA
designator C?  ValueDisplayed: 0.22µF  (hidden comment: C3216X5R2A224K115AA)
CAP, CERM, 0.22 µF, 100 V,+/- 10%, X5R, 1206; Manufacturer: TDK; Polarized: N; CompType: Capacitor; Value: 0.22uF; U/M: EA; Cap_F: 0.00000022; Tolerance_%: 10; ESR_ohm: 0.01493; Value1: 0.01493 ohm; VDC_V: 100; Value2: 100V; IRMS_A: 1.89056; TaMin_C: -55; TaMax_C: 85; Cap_Case: 1206; SizeArea_mm2: 5.12; SizeAreaWB_mm2: 10.92; SizeX_mm: 3.2; SizeY_mm: 1.6; SizeZ_mm: 1.35; AEC Category: Q200
signal-integrity model Cap
simulation model Cap
footprint 1206
footprint 1206M
footprint 1206L
pins: 1, 2

## C3216X5R2A334K130AA
designator C?  ValueDisplayed: 0.33µF  (hidden comment: C3216X5R2A334K130AA)
CAP, CERM, 0.33 µF, 100 V,+/- 10%, X5R, 1206; Manufacturer: TDK; Polarized: N; CompType: Capacitor; Value: 0.33uF; U/M: EA; Cap_F: 0.00000033; Tolerance_%: 10; ESR_ohm: 0.011504; Value1: 0.011504 ohm; VDC_V: 100; Value2: 100V; IRMS_A: 2.14919; TaMin_C: -55; TaMax_C: 85; Cap_Case: 1206; SizeArea_mm2: 5.12; SizeAreaWB_mm2: 10.92; SizeX_mm: 3.2; SizeY_mm: 1.6; SizeZ_mm: 1.5; AEC Category: Q200
signal-integrity model Cap
simulation model Cap
footprint 1206_150
footprint 1206_150M
footprint 1206_150L
pins: 1, 2

## C3216X5R2A474K160AA
designator C?  ValueDisplayed: 0.47µF  (hidden comment: C3216X5R2A474K160AA)
CAP, CERM, 0.47 µF, 100 V,+/- 10%, X5R, 1206; Manufacturer: TDK; Polarized: N; CompType: Capacitor; Value: 0.47uF; U/M: EA; Cap_F: 0.00000047; Tolerance_%: 10; ESR_ohm: 0.007558; Value1: 0.007558 ohm; VDC_V: 100; Value2: 100V; IRMS_A: 2.64716; TaMin_C: -55; TaMax_C: 85; Cap_Case: 1206; SizeArea_mm2: 5.12; SizeAreaWB_mm2: 10.92; SizeX_mm: 3.2; SizeY_mm: 1.6; SizeZ_mm: 1.8; AEC Category: Q200
signal-integrity model Cap
simulation model Cap
footprint 1206_180
footprint 1206_180M
footprint 1206_180L
pins: 1, 2

## C3216X5R2A684K160AA
designator C?  ValueDisplayed: 0.68µF  (hidden comment: C3216X5R2A684K160AA)
CAP, CERM, 0.68 µF, 100 V,+/- 10%, X5R, 1206; Manufacturer: TDK; Polarized: N; CompType: Capacitor; Value: 0.68uF; U/M: EA; Cap_F: 0.00000068; Tolerance_%: 10; ESR_ohm: 0.007371; Value1: 0.007371 ohm; VDC_V: 100; Value2: 100V; IRMS_A: 2.67843; TaMin_C: -55; TaMax_C: 85; Cap_Case: 1206; SizeArea_mm2: 5.12; SizeAreaWB_mm2: 10.92; SizeX_mm: 3.2; SizeY_mm: 1.6; SizeZ_mm: 1.8; AEC Category: Q200
signal-integrity model Cap
simulation model Cap
footprint 1206_180
footprint 1206_180M
footprint 1206_180L
pins: 1, 2

## C3216X6S0G107M160AC
designator C?  ValueDisplayed: 100µF  (hidden comment: C3216X6S0G107M160AC)
CAP, CERM, 100 µF, 4 V,+/- 20%, X6S, 1206; Manufacturer: TDK; Polarized: N; CompType: Capacitor; Value: 100uF; U/M: EA; Cap_F: 0.0001; Tolerance_%: 20; ESR_ohm: 0.002838; Value1: 0.002838 ohm; VDC_V: 4; Value2: 4V; IRMS_A: 4.30694; TaMin_C: -55; TaMax_C: 105; Cap_Case: 1206; SizeArea_mm2: 5.12; SizeAreaWB_mm2: 10.92; SizeX_mm: 3.2; SizeY_mm: 1.6; SizeZ_mm: 1.9; AEC Category: Q200
signal-integrity model Cap
simulation model Cap
footprint 1206_190
footprint 1206_190M
footprint 1206_190L
pins: 1, 2

## C3216X6S0G686M160AC
designator C?  ValueDisplayed: 68µF  (hidden comment: C3216X6S0G686M160AC)
CAP, CERM, 68 µF, 4 V,+/- 20%, X6S, 1206; Manufacturer: TDK; Polarized: N; CompType: Capacitor; Value: 68uF; U/M: EA; Cap_F: 0.000068; Tolerance_%: 20; ESR_ohm: 0.003494; Value1: 0.003494 ohm; VDC_V: 4; Value2: 4V; IRMS_A: 3.8813; TaMin_C: -55; TaMax_C: 105; Cap_Case: 1206; SizeArea_mm2: 5.12; SizeAreaWB_mm2: 10.92; SizeX_mm: 3.2; SizeY_mm: 1.6; SizeZ_mm: 1.9; AEC Category: Q200
signal-integrity model Cap
simulation model Cap
footprint 1206_190
footprint 1206_190M
footprint 1206_190L
pins: 1, 2

## C3216X6S1A226M160AB
designator C?  ValueDisplayed: 22µF  (hidden comment: C3216X6S1A226M160AB)
CAP, CERM, 22 µF, 10 V,+/- 20%, X6S, 1206; Manufacturer: TDK; Polarized: N; CompType: Capacitor; Value: 22uF; U/M: EA; Cap_F: 0.000022; Tolerance_%: 20; ESR_ohm: 0.002398; Value1: 0.002398 ohm; VDC_V: 10; Value2: 10V; IRMS_A: 4.68507; TaMin_C: -55; TaMax_C: 105; Cap_Case: 1206; SizeArea_mm2: 5.12; SizeAreaWB_mm2: 10.92; SizeX_mm: 3.2; SizeY_mm: 1.6; SizeZ_mm: 1.8; AEC Category: Q200
signal-integrity model Cap
simulation model Cap
footprint 1206_180
footprint 1206_180M
footprint 1206_180L
pins: 1, 2

## C3216X6S1A336M160AC
designator C?  ValueDisplayed: 33µF  (hidden comment: C3216X6S1A336M160AC)
CAP, CERM, 33 µF, 10 V,+/- 20%, X6S, 1206; Manufacturer: TDK; Polarized: N; CompType: Capacitor; Value: 33uF; U/M: EA; Cap_F: 0.000033; Tolerance_%: 20; ESR_ohm: 0.002648; Value1: 0.002648 ohm; VDC_V: 10; Value2: 10V; IRMS_A: 4.45864; TaMin_C: -55; TaMax_C: 105; Cap_Case: 1206; SizeArea_mm2: 5.12; SizeAreaWB_mm2: 10.92; SizeX_mm: 3.2; SizeY_mm: 1.6; SizeZ_mm: 1.8; AEC Category: Q200
signal-integrity model Cap
simulation model Cap
footprint 1206_180
footprint 1206_180M
footprint 1206_180L
pins: 1, 2

## C3216X6S1A476M160AC
designator C?  ValueDisplayed: 47µF  (hidden comment: C3216X6S1A476M160AC)
CAP, CERM, 47 µF, 10 V,+/- 20%, X6S, 1206; Manufacturer: TDK; Polarized: N; CompType: Capacitor; Value: 47uF; U/M: EA; Cap_F: 0.000047; Tolerance_%: 20; ESR_ohm: 0.002082; Value1: 0.002082 ohm; VDC_V: 10; Value2: 10V; IRMS_A: 5.02786; TaMin_C: -55; TaMax_C: 105; Cap_Case: 1206; SizeArea_mm2: 5.12; SizeAreaWB_mm2: 10.92; SizeX_mm: 3.2; SizeY_mm: 1.6; SizeZ_mm: 1.8; AEC Category: Q200
signal-integrity model Cap
simulation model Cap
footprint 1206_180
footprint 1206_180M
footprint 1206_180L
pins: 1, 2

## C3216X6S1C156M160AC
designator C?  ValueDisplayed: 15µF  (hidden comment: C3216X6S1C156M160AC)
CAP, CERM, 15 µF, 16 V,+/- 20%, X6S, 1206; Manufacturer: TDK; Polarized: N; CompType: Capacitor; Value: 15uF; U/M: EA; Cap_F: 0.000015; Tolerance_%: 20; ESR_ohm: 0.002667; Value1: 0.002667 ohm; VDC_V: 16; Value2: 16V; IRMS_A: 4.44289; TaMin_C: -55; TaMax_C: 105; Cap_Case: 1206; SizeArea_mm2: 5.12; SizeAreaWB_mm2: 10.92; SizeX_mm: 3.2; SizeY_mm: 1.6; SizeZ_mm: 1.8; AEC Category: Q200
signal-integrity model Cap
simulation model Cap
footprint 1206_180
footprint 1206_180M
footprint 1206_180L
pins: 1, 2

## C3216X6S1H155K160AB
designator C?  ValueDisplayed: 1.5µF  (hidden comment: C3216X6S1H155K160AB)
CAP, CERM, 1.5 µF, 50 V,+/- 10%, X6S, 1206; Manufacturer: TDK; Polarized: N; CompType: Capacitor; Value: 1.5uF; U/M: EA; Cap_F: 0.0000015; Tolerance_%: 10; ESR_ohm: 0.007741; Value1: 0.007741 ohm; VDC_V: 50; Value2: 50V; IRMS_A: 2.61033; TaMin_C: -55; TaMax_C: 105; Cap_Case: 1206; SizeArea_mm2: 5.12; SizeAreaWB_mm2: 10.92; SizeX_mm: 3.2; SizeY_mm: 1.6; SizeZ_mm: 1.8; AEC Category: Q200
signal-integrity model Cap
simulation model Cap
footprint 1206_180
footprint 1206_180M
footprint 1206_180L
pins: 1, 2

## C3216X6S1H225K160AB
designator C?  ValueDisplayed: 2.2µF  (hidden comment: C3216X6S1H225K160AB)
CAP, CERM, 2.2 µF, 50 V,+/- 10%, X6S, 1206; Manufacturer: TDK; Polarized: N; CompType: Capacitor; Value: 2.2uF; U/M: EA; Cap_F: 0.0000022; Tolerance_%: 10; ESR_ohm: 0.005887; Value1: 0.005887 ohm; VDC_V: 50; Value2: 50V; IRMS_A: 2.99226; TaMin_C: -55; TaMax_C: 105; Cap_Case: 1206; SizeArea_mm2: 5.12; SizeAreaWB_mm2: 10.92; SizeX_mm: 3.2; SizeY_mm: 1.6; SizeZ_mm: 1.8; AEC Category: Q200
signal-integrity model Cap
simulation model Cap
footprint 1206_180
footprint 1206_180M
footprint 1206_180L
pins: 1, 2

## C3216X6S1H335K160AB
designator C?  ValueDisplayed: 3.3µF  (hidden comment: C3216X6S1H335K160AB)
CAP, CERM, 3.3 µF, 50 V,+/- 10%, X6S, 1206; Manufacturer: TDK; Polarized: N; CompType: Capacitor; Value: 3.3uF; U/M: EA; Cap_F: 0.0000033; Tolerance_%: 10; ESR_ohm: 0.004773; Value1: 0.004773 ohm; VDC_V: 50; Value2: 50V; IRMS_A: 3.3221; TaMin_C: -55; TaMax_C: 105; Cap_Case: 1206; SizeArea_mm2: 5.12; SizeAreaWB_mm2: 10.92; SizeX_mm: 3.2; SizeY_mm: 1.6; SizeZ_mm: 1.8; AEC Category: Q200
signal-integrity model Cap
simulation model Cap
footprint 1206_180
footprint 1206_180M
footprint 1206_180L
pins: 1, 2

## C3216X6S1H475K160AB
designator C?  ValueDisplayed: 4.7µF  (hidden comment: C3216X6S1H475K160AB)
CAP, CERM, 4.7 µF, 50 V,+/- 10%, X6S, 1206; Manufacturer: TDK; Polarized: N; CompType: Capacitor; Value: 4.7uF; U/M: EA; Cap_F: 0.0000047; Tolerance_%: 10; ESR_ohm: 0.003158; Value1: 0.003158 ohm; VDC_V: 50; Value2: 50V; IRMS_A: 4.08379; TaMin_C: -55; TaMax_C: 105; Cap_Case: 1206; SizeArea_mm2: 5.12; SizeAreaWB_mm2: 10.92; SizeX_mm: 3.2; SizeY_mm: 1.6; SizeZ_mm: 1.8; AEC Category: Q200
signal-integrity model Cap
simulation model Cap
footprint 1206_180
footprint 1206_180M
footprint 1206_180L
pins: 1, 2

## C3216X6S1V106K160AC
designator C?  ValueDisplayed: 10µF  (hidden comment: C3216X6S1V106K160AC)
CAP, CERM, 10 µF, 35 V,+/- 10%, X6S, 1206; Manufacturer: TDK; Polarized: N; CompType: Capacitor; Value: 10uF; U/M: EA; Cap_F: 0.00001; Tolerance_%: 10; ESR_ohm: 0.002229; Value1: 0.002229 ohm; VDC_V: 35; Value2: 35V; IRMS_A: 4.85932; TaMin_C: -55; TaMax_C: 105; Cap_Case: 1206; SizeArea_mm2: 5.12; SizeAreaWB_mm2: 10.92; SizeX_mm: 3.2; SizeY_mm: 1.6; SizeZ_mm: 1.8; AEC Category: Q200
signal-integrity model Cap
simulation model Cap
footprint 1206_180
footprint 1206_180M
footprint 1206_180L
pins: 1, 2

## C3216X6S1V475K085AC
designator C?  ValueDisplayed: 4.7µF  (hidden comment: C3216X6S1V475K085AC)
CAP, CERM, 4.7 µF, 35 V,+/- 10%, X6S, 1206; Manufacturer: TDK; Polarized: N; CompType: Capacitor; Value: 4.7uF; U/M: EA; Cap_F: 0.0000047; Tolerance_%: 10; ESR_ohm: 0.003785; Value1: 0.003785 ohm; VDC_V: 35; Value2: 35V; IRMS_A: 3.73011; TaMin_C: -55; TaMax_C: 105; Cap_Case: 1206; SizeArea_mm2: 5.12; SizeAreaWB_mm2: 10.92; SizeX_mm: 3.2; SizeY_mm: 1.6; SizeZ_mm: 1.35; AEC Category: Q200
signal-integrity model Cap
simulation model Cap
footprint 1206
footprint 1206M
footprint 1206L
pins: 1, 2

## C3216X6S1V685K160AC
designator C?  ValueDisplayed: 6.8µF  (hidden comment: C3216X6S1V685K160AC)
CAP, CERM, 6.8 µF, 35 V,+/- 10%, X6S, 1206; Manufacturer: TDK; Polarized: N; CompType: Capacitor; Value: 6.8uF; U/M: EA; Cap_F: 0.0000068; Tolerance_%: 10; ESR_ohm: 0.003202; Value1: 0.003202 ohm; VDC_V: 35; Value2: 35V; IRMS_A: 4.05527; TaMin_C: -55; TaMax_C: 105; Cap_Case: 1206; SizeArea_mm2: 5.12; SizeAreaWB_mm2: 10.92; SizeX_mm: 3.2; SizeY_mm: 1.6; SizeZ_mm: 1.8; AEC Category: Q200
signal-integrity model Cap
simulation model Cap
footprint 1206_180
footprint 1206_180M
footprint 1206_180L
pins: 1, 2

## C3216X7R1A106K085AC
designator C?  ValueDisplayed: 10µF  (hidden comment: C3216X7R1A106K085AC)
CAP, CERM, 10 µF, 10 V,+/- 10%, X7R, 1206; Manufacturer: TDK; Polarized: N; CompType: Capacitor; Value: 10uF; U/M: EA; Cap_F: 0.00001; Tolerance_%: 10; ESR_ohm: 0.002454; Value1: 0.002454 ohm; Value2: 10V; IRMS_A: 4.63182; TaMin_C: -55; TaMax_C: 125; Cap_Case: 1206; SizeArea_mm2: 5.12; SizeAreaWB_mm2: 10.92; SizeX_mm: 3.2; SizeY_mm: 1.6; SizeZ_mm: 1.35; AEC Category: Q200
signal-integrity model Cap
simulation model Cap
footprint 1206
footprint 1206M
footprint 1206L
pins: 1, 2

## C3216X7R1A106M085AC
designator C?  ValueDisplayed: 10µF  (hidden comment: C3216X7R1A106M085AC)
CAP, CERM, 10 µF, 10 V,+/- 10%, X7R, 1206; Manufacturer: TDK; Polarized: N; CompType: Capacitor; Value: 10uF; U/M: EA; Cap_F: 0.00001; Tolerance_%: 10; Value2: 10V; TaMin_C: -55; TaMax_C: 125; Cap_Case: 1206; SizeArea_mm2: 5.12; SizeAreaWB_mm2: 10.92; SizeX_mm: 3.2; SizeY_mm: 1.6; SizeZ_mm: 1.35; AEC Category: Q200
signal-integrity model Cap
simulation model Cap
footprint 1206
footprint 1206M
footprint 1206L
pins: 1, 2

## C3216X7R1A106M160AC
designator C?  ValueDisplayed: 10µF  (hidden comment: C3216X7R1A106M160AC)
CAP, CERM, 10 µF, 10 V,+/- 20%, X7R, 1206; Manufacturer: TDK; Polarized: N; CompType: Capacitor; Value: 10uF; U/M: EA; Cap_F: 0.00001; Tolerance_%: 20; ESR_ohm: 0.0046; Value1: 0.0046 ohm; VDC_V: 10; Value2: 10V; TaMin_C: -55; TaMax_C: 125; Cap_Case: 1206; SizeArea_mm2: 5.12; SizeAreaWB_mm2: 10.92; SizeX_mm: 3.2; SizeY_mm: 1.6; SizeZ_mm: 1.35; AEC Category: Q200; Green_Lifecycle: NRND; Green_REACh: Passed
signal-integrity model Cap
simulation model Cap
footprint 1206
footprint 1206M
footprint 1206L
pins: 1, 2

## C3216X7R1C106K160AC
designator C?  ValueDisplayed: 10µF  (hidden comment: C3216X7R1C106K160AC)
CAP, CERM, 10 µF, 16 V,+/- 10%, X7R, 1206; Manufacturer: TDK; Polarized: N; CompType: Capacitor; Value: 10uF; U/M: EA; Cap_F: 0.00001; Tolerance_%: 10; VDC_V: 16; Value2: 16V; TaMin_C: -55; TaMax_C: 125; Cap_Case: 1206; SizeArea_mm2: 5.12; SizeAreaWB_mm2: 10.92; SizeX_mm: 3.2; SizeY_mm: 1.6; SizeZ_mm: 1.9; AEC Category: Q200; Green_Lifecycle: Active; Green_REACh: Passed
signal-integrity model Cap
simulation model Cap
footprint 1206_190
footprint 1206_190M
footprint 1206_190L
pins: 1, 2

## C3216X7R1E105K085AA
designator C?  ValueDisplayed: 1µF  (hidden comment: C3216X7R1E105K085AA)
CAP, CERM, 1 µF, 25 V,+/- 10%, X7R, 1206; Manufacturer: TDK; Polarized: N; CompType: Capacitor; Value: 1uF; U/M: EA; Cap_F: 0.000001; Tolerance_%: 10; ESR_ohm: 0.01; Value1: 0.01 ohm; VDC_V: 25; Value2: 25V; TaMin_C: -55; TaMax_C: 125; Cap_Case: 1206; SizeArea_mm2: 5.12; SizeAreaWB_mm2: 10.92; SizeX_mm: 3.2; SizeY_mm: 1.6; SizeZ_mm: 1.35; AEC Category: Q200; Green_Lifecycle: NRND; Green_REACh: Passed
signal-integrity model Cap
simulation model Cap
footprint 1206
footprint 1206M
footprint 1206L
pins: 1, 2

## C3216X7R1E106M160AE
designator C?  ValueDisplayed: 10µF  (hidden comment: C3216X7R1E106M160AE)
CAP, CERM, 10 µF, 25 V,+/- 20%, X7R, 1206; Manufacturer: TDK; Polarized: N; CompType: Capacitor; Value: 10uF; U/M: EA; Cap_F: 0.00001; Tolerance_%: 20; VDC_V: 25; Value2: 25V; TaMin_C: -55; TaMax_C: 125; Cap_Case: 1206; SizeArea_mm2: 5.12; SizeAreaWB_mm2: 10.92; SizeX_mm: 3.2; SizeY_mm: 1.6; SizeZ_mm: 1.9; AEC Category: Q200; Green_Lifecycle: Active; Green_REACh: Passed
signal-integrity model Cap
simulation model Cap
footprint 1206_190
footprint 1206_190M
footprint 1206_190L
pins: 1, 2

## C3216X7R1E475K085AB
designator C?  ValueDisplayed: 4.7µF  (hidden comment: C3216X7R1E475K085AB)
CAP, CERM, 4.7 µF, 25 V,+/- 10%, X7R, 1206; Manufacturer: TDK; Polarized: N; CompType: Capacitor; Value: 4.7uF; U/M: EA; Cap_F: 0.0000047; Tolerance_%: 10; VDC_V: 25; Value2: 25V; TaMin_C: -55; TaMax_C: 125; Cap_Case: 1206; SizeArea_mm2: 5.12; SizeAreaWB_mm2: 10.92; SizeX_mm: 3.2; SizeY_mm: 1.6; SizeZ_mm: 1.35; AEC Category: Q200
signal-integrity model Cap
simulation model Cap
footprint 1206
footprint 1206M
footprint 1206L
pins: 1, 2

## C3216X7R1E475M160AC
designator C?  ValueDisplayed: 4.7µF  (hidden comment: C3216X7R1E475M160AC)
CAP, CERM, 4.7 µF, 25 V,+/- 20%, X7R, 1206; Manufacturer: TDK; Polarized: N; CompType: Capacitor; Value: 4.7uF; U/M: EA; Cap_F: 0.0000047; Tolerance_%: 20; VDC_V: 25; Value2: 25V; TaMin_C: -55; TaMax_C: 125; Cap_Case: 1206; SizeArea_mm2: 5.12; SizeAreaWB_mm2: 10.92; SizeX_mm: 3.2; SizeY_mm: 1.6; SizeZ_mm: 1.9; AEC Category: Q200; Green_Lifecycle: Active; Green_REACh: Passed
signal-integrity model Cap
simulation model Cap
footprint 1206_190
footprint 1206_190M
footprint 1206_190L
pins: 1, 2

## C3216X7R1H105K160AB
designator C?  ValueDisplayed: 1µF  (hidden comment: C3216X7R1H105K160AB)
CAP, CERM, 1 µF, 50 V,+/- 10%, X7R, 1206; Manufacturer: TDK; Polarized: N; CompType: Capacitor; Value: 1uF; U/M: EA; Cap_F: 0.000001; Tolerance_%: 10; ESR_ohm: 0.009289; Value1: 0.009289 ohm; VDC_V: 50; Value2: 50V; IRMS_A: 2.38446; TaMin_C: -55; TaMax_C: 125; Cap_Case: 1206; SizeArea_mm2: 5.12; SizeAreaWB_mm2: 10.92; SizeX_mm: 3.2; SizeY_mm: 1.6; SizeZ_mm: 1.8; AEC Category: Q200; Green_Lifecycle: NRND; Green_REACh: Passed
signal-integrity model Cap
simulation model Cap
footprint 1206_180
footprint 1206_180M
footprint 1206_180L
pins: 1, 2

## C3216X7R1H155K160AB
designator C?  ValueDisplayed: 1.5µF  (hidden comment: C3216X7R1H155K160AB)
CAP, CERM, 1.5 µF, 50 V,+/- 10%, X7R, 1206; Manufacturer: TDK; Polarized: N; CompType: Capacitor; Value: 1.5uF; U/M: EA; Cap_F: 0.0000015; Tolerance_%: 10; ESR_ohm: 0.007741; Value1: 0.007741 ohm; VDC_V: 50; Value2: 50V; IRMS_A: 2.61033; TaMin_C: -55; TaMax_C: 125; Cap_Case: 1206; SizeArea_mm2: 5.12; SizeAreaWB_mm2: 10.92; SizeX_mm: 3.2; SizeY_mm: 1.6; SizeZ_mm: 1.8; AEC Category: Q200
signal-integrity model Cap
simulation model Cap
footprint 1206_180
footprint 1206_180M
footprint 1206_180L
pins: 1, 2

## C3216X7R1H224K115AA
designator C?  ValueDisplayed: 0.22µF  (hidden comment: C3216X7R1H224K115AA)
CAP, CERM, 0.22 µF, 50 V,+/- 10%, X7R, 1206; Manufacturer: TDK; Polarized: N; CompType: Capacitor; Value: 0.22uF; U/M: EA; Cap_F: 0.00000022; Tolerance_%: 10; ESR_ohm: 0.022217; Value1: 0.022217 ohm; VDC_V: 50; Value2: 50V; IRMS_A: 1.5504; TaMin_C: -55; TaMax_C: 125; Cap_Case: 1206; SizeArea_mm2: 5.12; SizeAreaWB_mm2: 10.92; SizeX_mm: 3.2; SizeY_mm: 1.6; SizeZ_mm: 1.35; AEC Category: Q200
signal-integrity model Cap
simulation model Cap
footprint 1206
footprint 1206M
footprint 1206L
pins: 1, 2

## C3216X7R1H225K160AB
designator C?  ValueDisplayed: 2.2µF  (hidden comment: C3216X7R1H225K160AB)
CAP, CERM, 2.2 µF, 50 V,+/- 10%, X7R, 1206; Manufacturer: TDK; Polarized: N; CompType: Capacitor; Value: 2.2uF; U/M: EA; Cap_F: 0.0000022; Tolerance_%: 10; ESR_ohm: 0.005887; Value1: 0.005887 ohm; VDC_V: 50; Value2: 50V; IRMS_A: 2.99226; TaMin_C: -55; TaMax_C: 125; Cap_Case: 1206; SizeArea_mm2: 5.12; SizeAreaWB_mm2: 10.92; SizeX_mm: 3.2; SizeY_mm: 1.6; SizeZ_mm: 1.8; AEC Category: Q200
signal-integrity model Cap
simulation model Cap
footprint 1206_180
footprint 1206_180M
footprint 1206_180L
pins: 1, 2

## C3216X7R1H334K160AA
designator C?  ValueDisplayed: 0.33µF  (hidden comment: C3216X7R1H334K160AA)
CAP, CERM, 0.33 µF, 50 V,+/- 10%, X7R, 1206; Manufacturer: TDK; Polarized: N; CompType: Capacitor; Value: 0.33uF; U/M: EA; Cap_F: 0.00000033; Tolerance_%: 10; ESR_ohm: 0.01359; Value1: 0.01359 ohm; VDC_V: 50; Value2: 50V; IRMS_A: 1.97777; TaMin_C: -55; TaMax_C: 125; Cap_Case: 1206; SizeArea_mm2: 5.12; SizeAreaWB_mm2: 10.92; SizeX_mm: 3.2; SizeY_mm: 1.6; SizeZ_mm: 1.8; AEC Category: Q200; Green_Lifecycle: NRND; Green_REACh: Passed
signal-integrity model Cap
simulation model Cap
footprint 1206_180
footprint 1206_180M
footprint 1206_180L
pins: 1, 2

## C3216X7R1H335K160AC
designator C?  ValueDisplayed: 3.3µF  (hidden comment: C3216X7R1H335K160AC)
CAP, CERM, 3.3 µF, 50 V,+/- 10%, X7R, 1206; Manufacturer: TDK; Polarized: N; CompType: Capacitor; Value: 3.3uF; U/M: EA; Cap_F: 0.0000033; Tolerance_%: 10; VDC_V: 50; Value2: 50V; TaMin_C: -55; TaMax_C: 125; Cap_Case: 1206; SizeArea_mm2: 5.12; SizeAreaWB_mm2: 10.92; SizeX_mm: 3.2; SizeY_mm: 1.6; SizeZ_mm: 1.9; AEC Category: Q200; Green_Lifecycle: Active; Green_REACh: Passed
signal-integrity model Cap
simulation model Cap
footprint 1206_190
footprint 1206_190M
footprint 1206_190L
pins: 1, 2

## C3216X7R1H474K160AA
designator C?  ValueDisplayed: 0.47µF  (hidden comment: C3216X7R1H474K160AA)
CAP, CERM, 0.47 µF, 50 V,+/- 10%, X7R, 1206; Manufacturer: TDK; Polarized: N; CompType: Capacitor; Value: 0.47uF; U/M: EA; Cap_F: 0.00000047; Tolerance_%: 10; ESR_ohm: 0.009426; Value1: 0.009426 ohm; VDC_V: 50; Value2: 50V; IRMS_A: 2.37046; TaMin_C: -55; TaMax_C: 125; Cap_Case: 1206; SizeArea_mm2: 5.12; SizeAreaWB_mm2: 10.92; SizeX_mm: 3.2; SizeY_mm: 1.6; SizeZ_mm: 1.8; AEC Category: Q200; Green_Lifecycle: Active; Green_REACh: Passed
signal-integrity model Cap
simulation model Cap
footprint 1206_180
footprint 1206_180M
footprint 1206_180L
pins: 1, 2

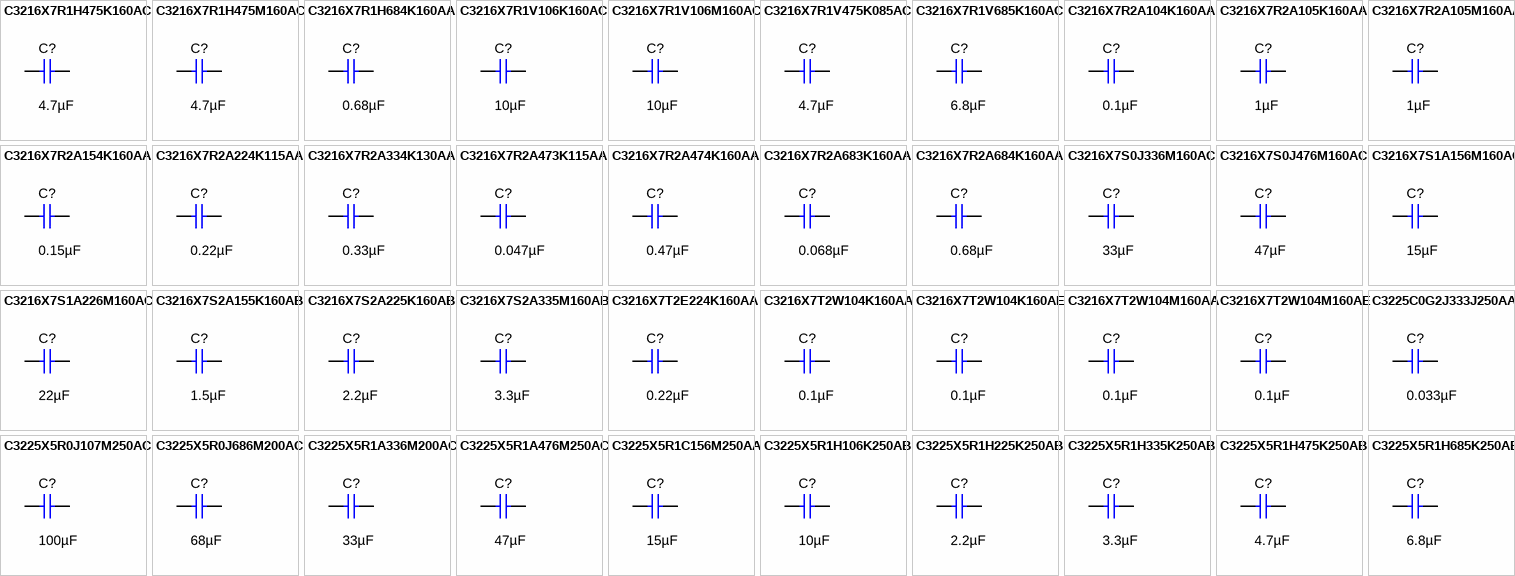
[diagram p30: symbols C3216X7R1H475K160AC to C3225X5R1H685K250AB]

## C3216X7R1H475K160AC
designator C?  ValueDisplayed: 4.7µF  (hidden comment: C3216X7R1H475K160AC)
CAP, CERM, 4.7 µF, 50 V,+/- 10%, X7R, 1206; Manufacturer: TDK; Polarized: N; CompType: Capacitor; Value: 4.7uF; U/M: EA; Cap_F: 0.0000047; Tolerance_%: 10; ESR_ohm: 0.003158; Value1: 0.003158 ohm; VDC_V: 50; Value2: 50V; IRMS_A: 4.08379; TaMin_C: -55; TaMax_C: 125; Cap_Case: 1206; SizeArea_mm2: 5.12; SizeAreaWB_mm2: 10.92; SizeX_mm: 3.2; SizeY_mm: 1.6; SizeZ_mm: 1.8; AEC Category: Q200
signal-integrity model Cap
simulation model Cap
footprint 1206_180
footprint 1206_180M
footprint 1206_180L
pins: 1, 2

## C3216X7R1H475M160AC
designator C?  ValueDisplayed: 4.7µF  (hidden comment: C3216X7R1H475M160AC)
CAP, CERM, 4.7 µF, 50 V,+/- 20%, X7R, 1206; Manufacturer: TDK; Polarized: N; CompType: Capacitor; Value: 4.7uF; U/M: EA; Cap_F: 0.0000047; Tolerance_%: 20; VDC_V: 50; Value2: 50V; TaMin_C: -55; TaMax_C: 125; Cap_Case: 1206; SizeArea_mm2: 5.12; SizeAreaWB_mm2: 10.92; SizeX_mm: 3.2; SizeY_mm: 1.6; SizeZ_mm: 1.9; AEC Category: Q200; Green_Lifecycle: Active; Green_REACh: Passed
signal-integrity model Cap
simulation model Cap
footprint 1206_190
footprint 1206_190M
footprint 1206_190L
pins: 1, 2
